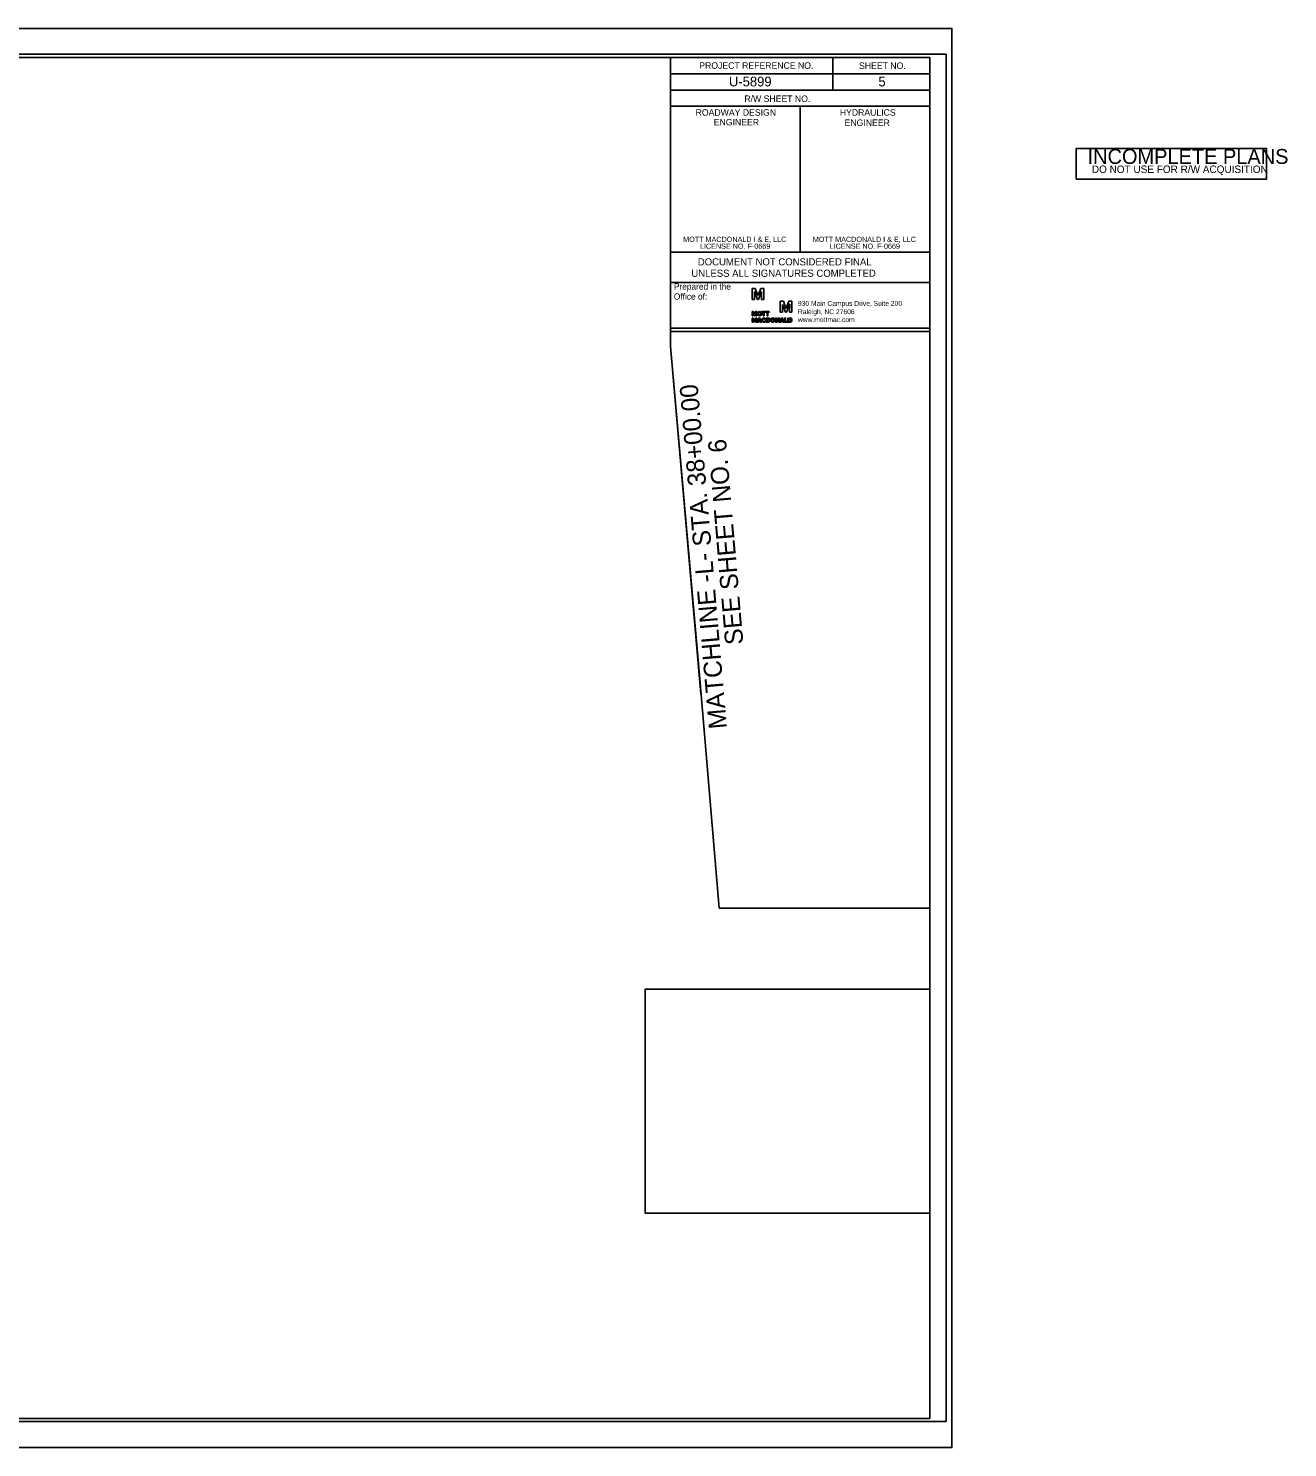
# Model space of a CAD drawing. Extents: x 1619045 to 1620988, y 897376 to 898471.
# Drawn here: x 1620016 to 1620988, y 897376 to 898471 of the extents above; entities that cross this region are included whole.
import ezdxf

# ---------------------------------------------------------------- set-up
doc = ezdxf.new("R2010")
doc.units = 0
for name, color, linetype in [('Matchline', 7, 'Continuous'), ('Matchline Text', 7, 'Continuous'), ('Old_Level_2', 7, 'Continuous'), ('Old_Level_42', 7, 'Continuous'), ('Old_Level_45', 7, 'Continuous'), ('Sheet Cutting Line CELL', 7, 'Continuous'), ('Sheet Data Field CELL', 7, 'Continuous'), ('Sheet Layout Plan Border', 7, 'Continuous'), ('Sheet Plan CELL', 7, 'Continuous'), ('Sheet Plan Layout CELL', 7, 'Continuous'), ('Sheet Plot Border Inside CELL', 7, 'Continuous'), ('Sheet Plot Border Outside CELL', 7, 'Continuous'), ('Sheet Sticker Exception Certification CELL', 7, 'Continuous'), ('Sheet Sticker Incomplete CELL', 7, 'Continuous')]:
    doc.layers.add(name, color=color, linetype=linetype)

msp = doc.modelspace()

# ---------------------------------------------------------------- linework, layer by layer
at = {"layer": 'Matchline'}
msp.add_line((1620535.2, 897957.3), (1620511.8, 898225.2), dxfattribs=at)
at = {"layer": 'Old_Level_2'}
for p, q in [((1620577.1, 898270.1), (1620574.6, 898270.1)), ((1620574.6, 898270.1), (1620574.6, 898261.6)), ((1620574.6, 898261.6), (1620576.4, 898261.6)), ((1620576.4, 898261.6), (1620576.4, 898267.7)), ((1620576.4, 898267.7), (1620576.4, 898267.7)), ((1620576.4, 898267.7), (1620578.8, 898261.6)), ((1620579.2, 898264.9), (1620577.1, 898270.1)), ((1620578.8, 898261.6), (1620579.6, 898261.6)), ((1620579.2, 898264.8), (1620579.2, 898264.9)), ((1620579.3, 898264.8), (1620579.2, 898264.8)), ((1620581.3, 898270.1), (1620579.3, 898264.9)), ((1620579.3, 898264.9), (1620579.3, 898264.8)), ((1620579.6, 898261.6), (1620582, 898267.8)), ((1620583.8, 898270.1), (1620581.3, 898270.1)), ((1620582, 898267.8), (1620582, 898267.8)), ((1620582, 898267.8), (1620582, 898261.6)), ((1620582, 898261.6), (1620583.8, 898261.6)), ((1620583.8, 898261.6), (1620583.8, 898270.1)), ((1620575.6, 898252.3), (1620574.6, 898252.3)), ((1620574.6, 898252.3), (1620574.6, 898249.1)), ((1620575.3, 898249.1), (1620575.3, 898251.4)), ((1620575.3, 898251.4), (1620575.3, 898251.4)), ((1620575.3, 898251.4), (1620576.2, 898249.1)), ((1620576.4, 898250.3), (1620575.6, 898252.3)), ((1620577.2, 898252.3), (1620576.4, 898250.3)), ((1620576.6, 898249.1), (1620577.5, 898251.4)), ((1620578.2, 898252.3), (1620577.2, 898252.3)), ((1620577.5, 898251.4), (1620577.5, 898251.4)), ((1620577.5, 898251.4), (1620577.5, 898249.1)), ((1620577.5, 898251.4), (1620577.5, 898251.4)), ((1620577.5, 898251.4), (1620577.5, 898251.4)), ((1620578.2, 898249.1), (1620578.2, 898252.3)), ((1620588.9, 898251.4), (1620588.9, 898251.4)), ((1620598.8, 898260.2), (1620596.2, 898260.2)), ((1620596.2, 898260.2), (1620596.2, 898251.7)), ((1620596.2, 898251.7), (1620598, 898251.7)), ((1620598, 898251.7), (1620598, 898257.8)), ((1620598, 898257.8), (1620598.1, 898257.8)), ((1620598.1, 898257.8), (1620600.5, 898251.7)), ((1620600.8, 898255), (1620598.8, 898260.2)), ((1620600.5, 898251.7), (1620601.2, 898251.7)), ((1620600.8, 898254.9), (1620600.8, 898255)), ((1620600.9, 898254.9), (1620600.8, 898254.9)), ((1620602.9, 898260.2), (1620600.9, 898255)), ((1620600.9, 898255), (1620600.9, 898254.9)), ((1620601.2, 898251.7), (1620603.6, 898257.9)), ((1620605.4, 898260.2), (1620602.9, 898260.2)), ((1620603.6, 898257.9), (1620603.7, 898257.9)), ((1620603.7, 898257.9), (1620603.6, 898251.7)), ((1620603.6, 898251.7), (1620605.4, 898251.7)), ((1620605.4, 898251.7), (1620605.4, 898260.2)), ((1620574.6, 898249.1), (1620575.3, 898249.1)), ((1620575.6, 898247.3), (1620574.6, 898247.3)), ((1620574.6, 898247.3), (1620574.6, 898244)), ((1620574.6, 898244), (1620575.3, 898244)), ((1620575.3, 898244), (1620575.3, 898246.4)), ((1620575.3, 898246.4), (1620575.3, 898246.4)), ((1620575.3, 898246.4), (1620576.2, 898244)), ((1620576.4, 898245.2), (1620575.6, 898247.3)), ((1620576.2, 898249.1), (1620576.6, 898249.1)), ((1620576.2, 898244), (1620576.6, 898244)), ((1620577.2, 898247.3), (1620576.4, 898245.2)), ((1620576.6, 898244), (1620577.5, 898246.4)), ((1620578.2, 898247.3), (1620577.2, 898247.3)), ((1620577.5, 898249.1), (1620578.2, 898249.1)), ((1620577.5, 898246.4), (1620577.5, 898246.4)), ((1620577.5, 898246.4), (1620577.5, 898244)), ((1620577.5, 898244), (1620578.2, 898244)), ((1620578.2, 898244), (1620578.2, 898247.3)), ((1620585, 898244.7), (1620584.4, 898245)), ((1620584.5, 898246.2), (1620585.1, 898246.5)), ((1620587, 898247.3), (1620585.5, 898247.3)), ((1620585.5, 898247.3), (1620585.5, 898245.6)), ((1620585.5, 898245.6), (1620585.5, 898244)), ((1620585.5, 898244), (1620587, 898244)), ((1620586.2, 898244.7), (1620586.2, 898246.7)), ((1620586.2, 898246.7), (1620587, 898246.7)), ((1620587, 898244.7), (1620586.2, 898244.7)), ((1620602.3, 898247.3), (1620602.3, 898247.3)), ((1620603.8, 898247.3), (1620602.3, 898247.3)), ((1620602.3, 898247.3), (1620602.3, 898245.6)), ((1620602.3, 898245.6), (1620602.3, 898244)), ((1620602.3, 898244), (1620603.8, 898244)), ((1620603, 898244.7), (1620603, 898246.7)), ((1620603, 898246.7), (1620603.8, 898246.7)), ((1620603.8, 898244.7), (1620603, 898244.7)), ((1620603.8, 898246.7), (1620603.8, 898246.7))]:
    msp.add_line(p, q, dxfattribs=at)
for points in [[(1620582.2, 898251.7), (1620583.2, 898251.7), (1620583.2, 898249.1), (1620583.9, 898249.1), (1620583.9, 898251.7), (1620584.8, 898251.7), (1620584.8, 898252.3), (1620582.2, 898252.3), (1620582.2, 898251.7)], [(1620585.2, 898251.7), (1620586.2, 898251.7), (1620586.2, 898249.1), (1620586.9, 898249.1), (1620586.9, 898251.7), (1620587.8, 898251.7), (1620587.8, 898252.3), (1620585.2, 898252.3), (1620585.2, 898251.7)], [(1620578.6, 898244), (1620579.3, 898244), (1620579.5, 898244.6), (1620580.9, 898244.6), (1620581.2, 898244), (1620581.9, 898244), (1620580.7, 898247.3), (1620579.8, 898247.3), (1620578.6, 898244)], [(1620579.7, 898245.2), (1620580.2, 898246.6), (1620580.8, 898245.2), (1620579.7, 898245.2)], [(1620593.5, 898246.1), (1620593.5, 898246.1), (1620595.1, 898244), (1620595.7, 898244), (1620595.7, 898247.3), (1620595, 898247.3), (1620595, 898245.2), (1620593.5, 898247.3), (1620592.8, 898247.3), (1620592.8, 898244), (1620593.5, 898244), (1620593.5, 898246.1)], [(1620596.1, 898244), (1620596.9, 898244), (1620597.1, 898244.6), (1620598.5, 898244.6), (1620598.7, 898244), (1620599.5, 898244), (1620598.2, 898247.3), (1620597.4, 898247.3), (1620596.1, 898244)], [(1620597.3, 898245.2), (1620597.8, 898246.6), (1620598.3, 898245.2), (1620597.3, 898245.2)], [(1620601.9, 898244), (1620601.9, 898244.6), (1620600.5, 898244.6), (1620600.5, 898247.3), (1620599.9, 898247.3), (1620599.9, 898244), (1620601.9, 898244)]]:
    msp.add_lwpolyline(points, dxfattribs=at)
msp.add_arc((1620603.8, 898245.7), 1.62, 270, 90, dxfattribs=at)
for centre, major_axis, ratio in [((1620580.4, 898250.7), (0, 1.62), 0.993118), ((1620580.4, 898250.7), (0, 1.06), 0.916103), ((1620590.6, 898245.7), (0, 1.62), 0.993118), ((1620590.6, 898245.7), (0, 1.06), 0.916103)]:
    msp.add_ellipse(centre, major_axis=major_axis, ratio=ratio, dxfattribs=at)
for centre, major_axis, ratio, start_param, end_param in [((1620583.7, 898245.7), (0, 1.62), 0.993118, 5.246647, 10.366427), ((1620583.7, 898245.7), (0, 1.06), 0.916103, 5.276876, 10.296021), ((1620587, 898245.7), (0, -1.62), 0.930276, 0, 3.141593), ((1620587, 898245.7), (0, -1.01), 0.900832, 0, 3.141593), ((1620603.8, 898245.7), (0, -1.01), 0.900832, 0, 3.141593)]:
    msp.add_ellipse(centre, major_axis=major_axis, ratio=ratio, start_param=start_param, end_param=end_param, dxfattribs=at)
at = {"layer": 'Old_Level_42'}
msp.add_lwpolyline([(1620711.8, 898239.4), (1620511.8, 898239.4), (1620511.8, 898274.7)], dxfattribs=at)
at = {"layer": 'Sheet Cutting Line CELL'}
for p, q in [((1620728.8, 898470.8), (1619045.3, 898470.8)), ((1619045.3, 897375.8), (1620728.8, 897375.8))]:
    msp.add_line(p, q, dxfattribs=at)
at = {"layer": 'Sheet Layout Plan Border'}
for points in [[(1619504.8, 898336.1), (1619262.1, 897919.5), (1619261.8, 897398.3), (1620711.8, 897398.3), (1620711.8, 897792), (1620549.3, 897792), (1620534.5, 897965.9), (1620511.8, 898225.2), (1620511.7, 898448.3), (1620082.8, 898448.3), (1619478.1, 898448.3), (1619466.3, 898432.9), (1619531.9, 898382.6)], [(1620711.8, 897729.5), (1620492.3, 897729.5), (1620492.3, 897556.6), (1620711.8, 897556.6)]]:
    msp.add_lwpolyline(points, close=True, dxfattribs=at)
at = {"layer": 'Sheet Plan CELL'}
for p, q in [((1620636.8, 898448.2), (1620636.8, 898423.2)), ((1620511.7, 898435.7), (1620711.8, 898435.7)), ((1620511.7, 898423.2), (1620711.8, 898423.2)), ((1620511.7, 898423.2), (1620511.7, 898410.7)), ((1620611.8, 898410.7), (1620611.8, 898298.3))]:
    msp.add_line(p, q, dxfattribs=at)
for points in [[(1620711.8, 898448.3), (1619211.8, 898448.3), (1619211.8, 897398.3), (1620711.8, 897398.3)], [(1619211.8, 897398.3), (1619211.8, 898448.3), (1620511.7, 898448.3), (1620511.8, 898298.2), (1620711.8, 898298.2), (1620711.8, 897398.3)], [(1620511.7, 898448.3), (1620711.8, 898448.3), (1620711.8, 898423.2), (1620511.7, 898423.2)], [(1620511.7, 898410.7), (1620611.8, 898410.7), (1620611.8, 898298.2), (1620511.8, 898298.2)], [(1620611.8, 898410.7), (1620711.8, 898410.7), (1620711.8, 898298.2), (1620611.8, 898298.2)]]:
    msp.add_lwpolyline(points, close=True, dxfattribs=at)
at = {"layer": 'Sheet Plan Layout CELL'}
msp.add_lwpolyline([(1619211.8, 898448.3), (1619211.8, 897398.3), (1620711.8, 897398.3), (1620711.8, 898236.8), (1620511.7, 898236.8), (1620511.7, 898448.3)], close=True, dxfattribs=at)
at = {"layer": 'Sheet Plot Border Inside CELL'}
msp.add_lwpolyline([(1619058.3, 897395.8), (1620724.3, 897395.8), (1620724.3, 898450.8), (1619058.3, 898450.8)], close=True, dxfattribs=at)
at = {"layer": 'Sheet Plot Border Outside CELL'}
msp.add_lwpolyline([(1619045.3, 897375.8), (1620728.8, 897375.8), (1620728.8, 898470.8), (1619045.3, 898470.8)], close=True, dxfattribs=at)
at = {"layer": 'Sheet Sticker Exception Certification CELL'}
for p, q in [((1620511.8, 898274.7), (1620511.8, 898298.2)), ((1620511.8, 898298.2), (1620711.8, 898298.2)), ((1620711.8, 898298.2), (1620711.8, 898274.7)), ((1620711.8, 898274.7), (1620511.8, 898274.7))]:
    msp.add_line(p, q, dxfattribs=at)
at = {"layer": 'Sheet Sticker Incomplete CELL'}
msp.add_lwpolyline([(1620824.5, 898354.5), (1620824.5, 898378), (1620971.5, 898378), (1620971.5, 898354.5)], close=True, dxfattribs=at)

# ---------------------------------------------------------------- texts
at = {"layer": 'Matchline Text'}
for s, p in [('MATCHLINE -L- STA. 38+00.00', (1620555.3, 897930.8)), ('SEE SHEET NO. 6', (1620568, 897995.8))]:
    msp.add_text(s, height=14, rotation=94.8761, dxfattribs=at).set_placement(p)
at = {"layer": 'Old_Level_2'}
for s, height, p in [('Prepared in the ', 4.819, (1620514.3, 898269.2)), ('Office of:', 4.82, (1620514.3, 898261.5))]:
    msp.add_text(s, height=height, dxfattribs=at).set_placement(p)
for s, p in [('930 Main Campus Drive, Suite 200', (1620610, 898256.7)), ('Raleigh, NC 27606', (1620610, 898250.3)), ('www.mottmac.com', (1620610, 898244.2))]:
    msp.add_text(s, height=3.75, rotation=360, dxfattribs=at).set_placement(p)
at = {"layer": 'Old_Level_45'}
for s, p in [('MOTT MACDONALD I & E, LLC', (1620521.5, 898306)), ('MOTT MACDONALD I & E, LLC', (1620621.5, 898306)), (' LICENSE NO. F-0669', (1620532.9, 898300.7)), (' LICENSE NO. F-0669', (1620632.9, 898300.7))]:
    msp.add_text(s, height=4.018, dxfattribs=at).set_placement(p)
at = {"layer": 'Sheet Data Field CELL'}
for s, p in [('U-5899', (1620556.8, 898426)), ('5', (1620672.1, 898426))]:
    msp.add_text(s, height=7.5, rotation=0, dxfattribs=at).set_placement(p)
at = {"layer": 'Sheet Plan CELL'}
for s, p in [('PROJECT REFERENCE NO.', (1620533.9, 898439.6)), ('SHEET NO.', (1620657.1, 898439.5)), ('R/W SHEET NO.', (1620568.7, 898414)), ('ROADWAY DESIGN', (1620531.1, 898403.4)), ('HYDRAULICS', (1620642.3, 898403.4)), ('ENGINEER', (1620545.1, 898395.9)), ('ENGINEER', (1620646, 898395.5))]:
    msp.add_text(s, height=5, rotation=0, dxfattribs=at).set_placement(p)
at = {"layer": 'Sheet Sticker Exception Certification CELL'}
for s, p in [('UNLESS ALL SIGNATURES COMPLETED', (1620527.8, 898279.1)), ('DOCUMENT NOT CONSIDERED FINAL', (1620532.8, 898287.9))]:
    msp.add_text(s, height=5.5, dxfattribs=at).set_placement(p)
at = {"layer": 'Sheet Sticker Incomplete CELL'}
for s, height, p in [('INCOMPLETE PLANS', 11.52, (1620833.4, 898366.2)), ('DO NOT USE FOR R/W ACQUISITION', 5.76, (1620836.7, 898359.2))]:
    msp.add_text(s, height=height, dxfattribs=at).set_placement(p)

doc.saveas('drawing.dxf')
